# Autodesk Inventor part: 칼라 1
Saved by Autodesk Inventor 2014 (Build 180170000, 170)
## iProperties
Created: 2026-04
Part Number: 칼라 1
Material: 일반
Document SubType Name: Modeling
Designer: dg
Density: 1 g/cm^3
Appearance: 기본값
Author: dg
Author: jhkim
Creation Date: 2026-03-27
Sending System: Autodesk Inventor 2026
Preprocessor: ST-DEVELOPER v20.1
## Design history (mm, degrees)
node "칼라 11"
node "솔리드1"
node "기준1"
